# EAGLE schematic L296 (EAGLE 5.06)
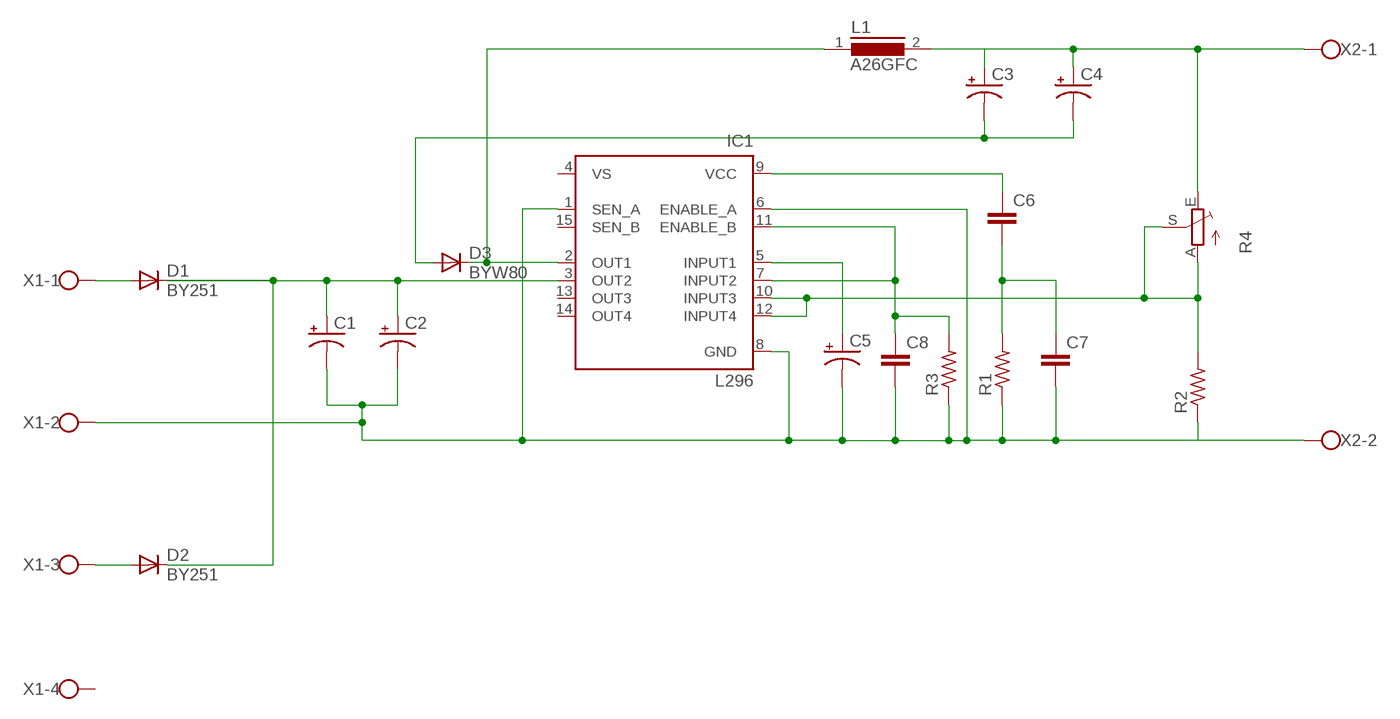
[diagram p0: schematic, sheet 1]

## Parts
C1  CPOL-USE7.5-16  [E7,5-16]
C2  CPOL-USE7.5-16  [E7,5-16]
C3  CPOL-USE5-13  [E5-13]
C4  CPOL-USE5-13  [E5-13]
C5  CPOL-USE5-6  [E5-6]
C6  C-EU050-025X075  [C050-025X075]
C7  C-EU050-025X075  [C050-025X075]
C8  C-EU050-025X075  [C050-025X075]
D1  BY251  [DO201-15]
D2  BY251  [DO201-15]
D3  BYW80  [TO220ACS]
IC1  L296  L298  [MULTIWATT-15]
L1  A26GFC  [A26GFC]
R1  R-US_0207/10  [0207/10]
R2  R-US_0207/10  [0207/10]
R3  R-US_0207/10  [0207/10]
R4  TRIM_EU-CA14H  [CA14H]
X1  W237-4  [W237-4]
X2  W237-102  [W237-102]

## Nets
N$1: D1.A X1.1
N$2: D2.A X1.3
N$3: C1.+ C2.+ D1.C D2.C IC1.3(OUT2)
N$4: D3.C IC1.2(OUT1) L1.1
N$6: C6.2 C7.1 R1.2
N$7: C5.+ IC1.5(INPUT1)
N$8: C1.- C2.- C5.- C7.2 C8.2 IC1.1(SEN_A) IC1.6(ENABLE_A) IC1.8(GND) R1.1 R2.1 R3.1 X1.2 X2.2
N$9: C8.1 IC1.7(INPUT2) IC1.11(ENABLE_B) R3.2
N$10: C6.1 IC1.9(VCC)
N$11: IC1.10(INPUT3) IC1.12(INPUT4) R2.2 R4.A R4.S
N$13: C3.+ C4.+ L1.2 R4.E X2.1
N$14: C3.- C4.- D3.A
Unconnected: IC1.13(OUT3) IC1.14(OUT4) IC1.15(SEN_B) X1.4

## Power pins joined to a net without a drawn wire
VS: IC1.4(VS)

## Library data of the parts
C1-C5 = resistor:CPOL-US: POLARIZED CAPACITOR, American symbol
C6-C8 = resistor:C-EU: CAPACITOR, European symbol
D1 D2 = diode:BY251: DIODE
D3 = diode:BYW80: DIODE
IC1 = st-microelectronics:L298: DUAL FULL-BRIDGE DRIVER
L1 = inductors:A26GFC: INDUCTOR
R1-R3 = resistor:R-US_: RESISTOR, American symbol
R4 = pot:TRIM_EU-: POTENTIOMETER
X1 = con-wago-500:W237-4: WAGO SCREW CLAMP
X2 = con-wago-500:W237-102: WAGO SCREW CLAMP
